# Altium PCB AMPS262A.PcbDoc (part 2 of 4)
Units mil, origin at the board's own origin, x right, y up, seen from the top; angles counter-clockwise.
Board outline 5314.96 x 4803.15 mil, 4 copper layers (Top Layer, GND, Copper Layer 3, Bottom Layer), stack 79.28 mil thick; 324 components, 156 nets, 943 pads, 1411 vias.
Unrouted connection lines stored in the file: 130.
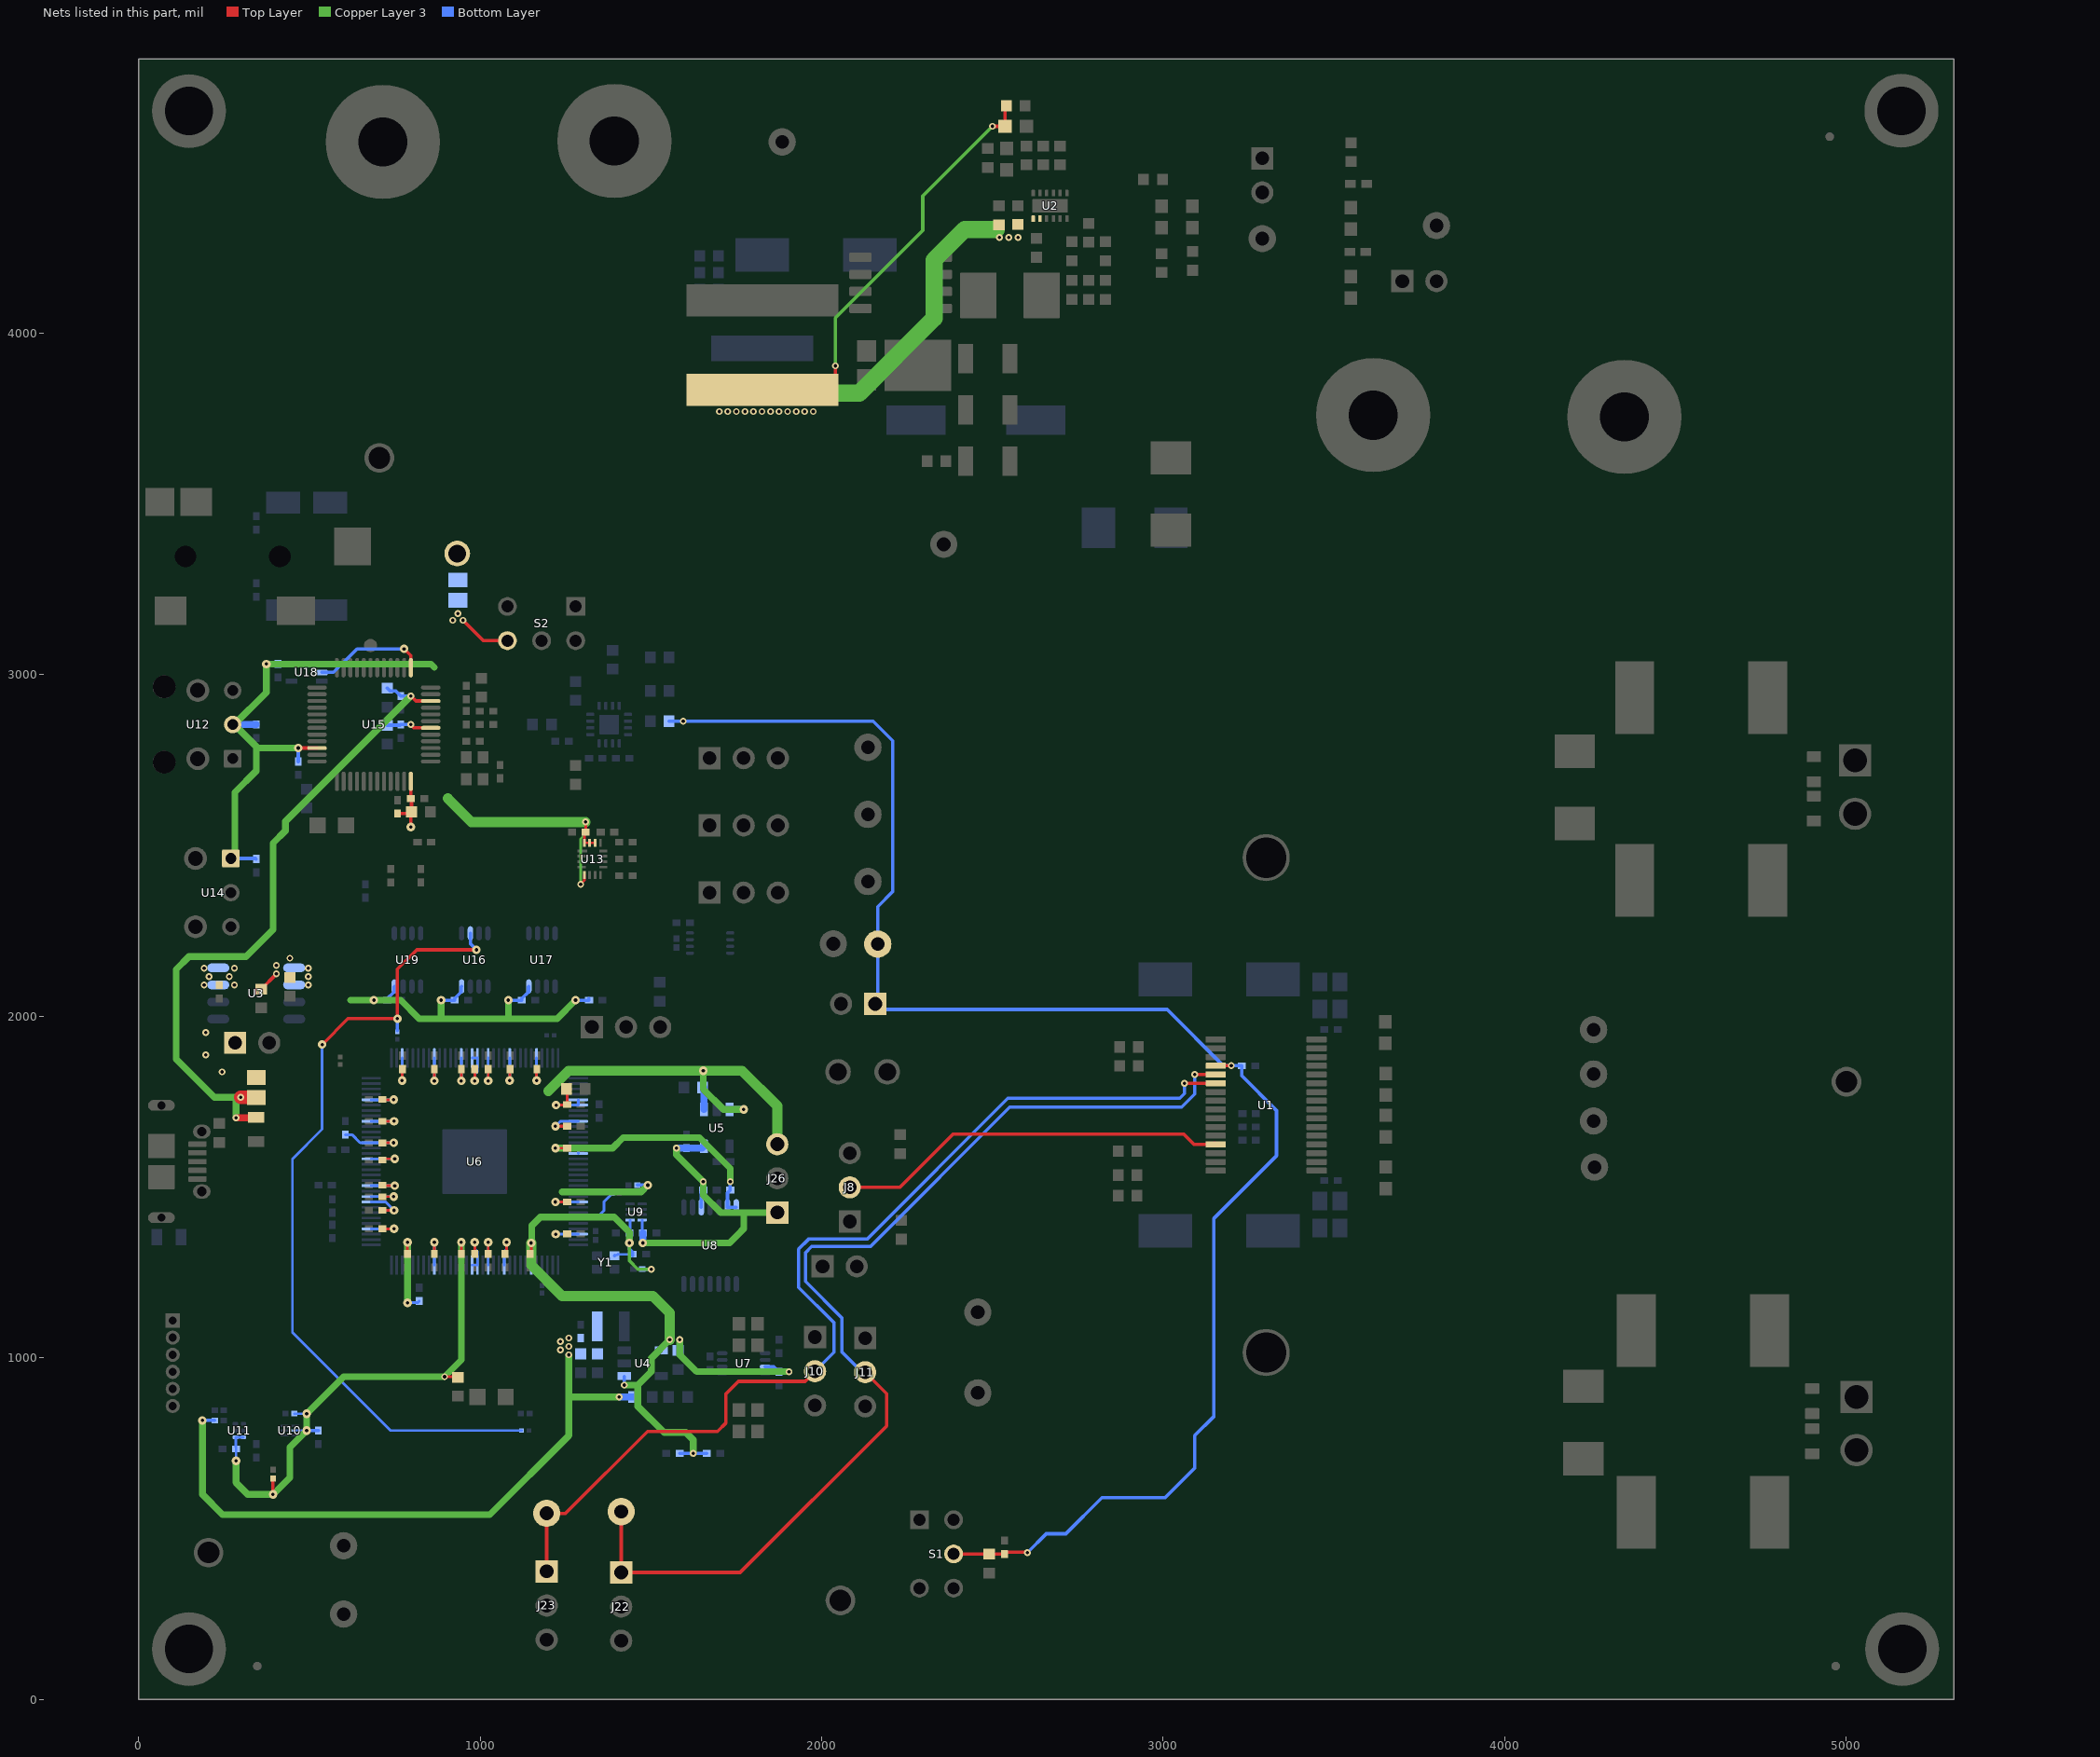
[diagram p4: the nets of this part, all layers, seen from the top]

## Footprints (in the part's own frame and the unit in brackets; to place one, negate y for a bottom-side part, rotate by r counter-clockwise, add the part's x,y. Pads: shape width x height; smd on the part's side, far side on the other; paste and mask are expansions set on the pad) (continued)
TQFP-128 [mm] "TQFP, 128-Leads, Body 14x14mm, Pitch 0.4mm"
  rrect50% 1.45x0.2 smd: 1(-7.7,6.2) 2(-7.7,5.8) 3(-7.7,5.4) 4(-7.7,5) 5(-7.7,4.6) 6(-7.7,4.2) 7(-7.7,3.8) 8(-7.7,3.4) 9(-7.7,3) 10(-7.7,2.6) 11(-7.7,2.2) 12(-7.7,1.8) 13(-7.7,1.4) 14(-7.7,1) 15(-7.7,0.6) 16(-7.7,0.2) 17(-7.7,-0.2) 18(-7.7,-0.6) 19(-7.7,-1) 20(-7.7,-1.4) 21(-7.7,-1.8) 22(-7.7,-2.2) 23(-7.7,-2.6) 24(-7.7,-3) 25(-7.7,-3.4) 26(-7.7,-3.8) 27(-7.7,-4.2) 28(-7.7,-4.6) 29(-7.7,-5) 30(-7.7,-5.4) 31(-7.7,-5.8) 32(-7.7,-6.2) 65(7.7,-6.2) 66(7.7,-5.8) 67(7.7,-5.4) 68(7.7,-5) 69(7.7,-4.6) 70(7.7,-4.2) 71(7.7,-3.8) 72(7.7,-3.4) 73(7.7,-3) 74(7.7,-2.6) 75(7.7,-2.2) 76(7.7,-1.8) 77(7.7,-1.4) 78(7.7,-1) 79(7.7,-0.6) 80(7.7,-0.2) 81(7.7,0.2) 82(7.7,0.6) 83(7.7,1) 84(7.7,1.4) 85(7.7,1.8) 86(7.7,2.2) 87(7.7,2.6) 88(7.7,3) 89(7.7,3.4) 90(7.7,3.8) 91(7.7,4.2) 92(7.7,4.6) 93(7.7,5) 94(7.7,5.4) 95(7.7,5.8) 96(7.7,6.2)
  rrect50% 0.2x1.45 smd: 33(-6.2,-7.7) 34(-5.8,-7.7) 35(-5.4,-7.7) 36(-5,-7.7) 37(-4.6,-7.7) 38(-4.2,-7.7) 39(-3.8,-7.7) 40(-3.4,-7.7) 41(-3,-7.7) 42(-2.6,-7.7) 43(-2.2,-7.7) 44(-1.8,-7.7) 45(-1.4,-7.7) 46(-1,-7.7) 47(-0.6,-7.7) 48(-0.2,-7.7) 49(0.2,-7.7) 50(0.6,-7.7) 51(1,-7.7) 52(1.4,-7.7) 53(1.8,-7.7) 54(2.2,-7.7) 55(2.6,-7.7) 56(3,-7.7) 57(3.4,-7.7) 58(3.8,-7.7) 59(4.2,-7.7) 60(4.6,-7.7) 61(5,-7.7) 62(5.4,-7.7) 63(5.8,-7.7) 64(6.2,-7.7) 97(6.2,7.7) 98(5.8,7.7) 99(5.4,7.7) 100(5,7.7) 101(4.6,7.7) 102(4.2,7.7) 103(3.8,7.7) 104(3.4,7.7) 105(3,7.7) 106(2.6,7.7) 107(2.2,7.7) 108(1.8,7.7) 109(1.4,7.7) 110(1,7.7) 111(0.6,7.7) 112(0.2,7.7) 113(-0.2,7.7) 114(-0.6,7.7) 115(-1,7.7) 116(-1.4,7.7) 117(-1.8,7.7) 118(-2.2,7.7) 119(-2.6,7.7) 120(-3,7.7) 121(-3.4,7.7) 122(-3.8,7.7) 123(-4.2,7.7) 124(-4.6,7.7) 125(-5,7.7) 126(-5.4,7.7) 127(-5.8,7.7) 128(-6.2,7.7)
  rrect2% 4.8x4.8 smd paste-4.8: 129(0,0)
  silkscreen extent -7.1,-7.1 7.1,7.1, body extent -7,-7 7,7, height 1.2
WE-PD_1210 [mm] "Wurth Elektronik recommended land pattern"
  rect 2.9x5.4 smd: 1(-4.95,0) 2(4.95,0)
  silkscreen extent -6,-6 6,6, body extent -6,-6 6,6, height 10.01
WEEE_Minimum [mil] "WEEElie bin"
  silkscreen extent -95,-172 99,104
XAL1010 [mm] "COILCRAFT"
  rect 2.38x11.31 smd: 1(-3.325,0) 2(3.325,0)
  silkscreen extent -5.3,-6 5.3,6, body extent -5.25,-5.9 5.25,5.9, height 10
XTAL_ABM10 [mm] "ABRACON"
  rect 0.8x0.9 smd: 1(-0.625,0.825) 2(-0.625,-0.825) 3(0.625,-0.825) 4(0.625,0.825)
  silkscreen extent -1.28,-0.13 1.05,1.52, body extent -1.05,-1.3 1.05,1.3, height 0.7

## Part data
C1 C10 C13 C21: library part CMP-0086459-1, "CAP CER 0.68UF 50V X7R 0805", Manufacturer="TDK Corporation", TempCo=15%, Tolerance_%=20%
C2 C7: library part CMP-0007842-2, "CAP, CERM, 10 uF, 35 V, +/- 10%, X5R, 0805", Alternate Manufacturer="CAL-CHIP ELECTRONICS, INC.", Alternate PartNumber=GMC21X5R106K35NT, Cap_Case=0805, Manufacturer=TDK, Supplier Part Number 1=445-14417-1-ND, TempCo=X5R, Tolerance_%=10%, Value1="0.002818 ohm", Value2=35V, ValueDisplayed=10uF
C3 C6: library part CMP-0007842-2, "CAP, CERM, 10 uF, 35 V, +/- 10%, X5R, 0805", Alternate Manufacturer="CAL-CHIP ELECTRONICS, INC.", Alternate PartNumber=GMC21X5R106K35NT, Cap_Case=0805, Manufacturer=TDK, PartNumber=C2012X5R1V106K085AC, Supplier Part Number 1=445-14417-1-ND, TempCo=X5R, Tolerance_%=10%, Value1="0.002818 ohm", Value2=35V, ValueDisplayed=10uF
C4 C5: library part CMP-0006325-2, "CAP, CERM, 0.1 uF, 50 V, +/- 10%, X7R, AEC-Q200 Grade 1, 0402", Cap_Case=0402, Manufacturer=TDK, Supplier Part Number 1=445-6899-1-ND, TempCo=X7R, Tolerance_%=10%, Value1="0.039064 ohm", Value2=50V, ValueDisplayed=0.1uF
C8 C9: library part CMP-0011092-1, "CAP, AL, 390 uF, 35 V, +/- 20%, 0.08 ohm, SMD", Cap_Case=10x10, Manufacturer=Nichicon, PartNumber=UCL1V391MNL1GS, Supplier Part Number 1=493-3960-1-ND, Tolerance_%=20%, Value1="0.08 ohm", Value2=35V, ValueDisplayed=390uF
C11: library part CMP-0006949-5, "CAP, CERM, 4.7 uF, 10 V, +/- 10%, X5R, 0603", Cap_Case=0603, Manufacturer=Kemet, PartNumber=C0603C475K8PACTU, Supplier Part Number 1=399-5503-1-ND, TempCo=X5R, Tolerance_%=10%, Value1="0.006 ohm", Value2=10V, ValueDisplayed=4.7uF
C12 C22: library part CMP-0006860-5, "CAP, CERM, 0.1 uF, 16 V, +/- 10%, X7R, 0603", Cap_Case=0603, Manufacturer=Kemet, PartNumber=C0603C104K4RACTU, Supplier Part Number 1=399-1096-1-ND, TempCo=X7R, Tolerance_%=10%, Value1=Unknown, Value2=16V, ValueDisplayed=0.1uF
C14 C16 C18 C20: library part CMP-0007050-4, "CAP, CERM, 0.47 uF, 50 V, +/- 10%, X7R, 0603", Cap_Case=0603, Manufacturer=TDK, Supplier Part Number 1=445-5952-1-ND, TempCo=X7R, Tolerance_%=10%, Value1="0.010974 ohm", Value2=50V, ValueDisplayed=0.47uF
C15 C17 C19: library part CMP-0082012-1, "CAP, CERM, 1 µF, 16 V,+/- 20%, X7R, 0603", Cap_Case=0603, Manufacturer=Samsung, Supplier Part Number 1=1276-6524-1-ND, TempCo=X7R, Tolerance_%=20%, Value2=16V, ValueDisplayed=1µF
C23: library part CMP-0012596-3, "CAP, Polymer Hybrid, 100 uF, 50 V, +/- 20%, 28 ohm, 10x10 SMD", Alternate Manufacturer="Cornell Dubilier Electronics (CDE)", Alternate PartNumber=HZA107M050G24VT-F, Manufacturer=Panasonic, PartNumber=EEHZC1H101P, Supplier Part Number 1=P15462CT-ND, Tolerance_%=20%, Value1="28 ohm", Value2=50V, ValueDisplayed=100uF
C24 C25 C26: library part CMP-0860569-1, "CAP, CERM, 10 µF, 25 V,+/- 10%, X5R, 0603", Alternate Manufacturer="CAL-CHIP ELECTRONICS, INC.", Alternate PartNumber=GMC10X5R106K25NT, Cap_Case=0603, Manufacturer=MuRata, TempCo=X5R, Tolerance_%=10%, Value2=25V, ValueDisplayed=10µF
C27: library part CMP-0080610-1, "CAP, CERM, 0.1 µF, 25 V,+/- 10%, X7R, AEC-Q200 Grade 1, 0402", Cap_Case=0402, Manufacturer=TDK, Supplier Part Number 1=445-6902-1-ND, TempCo=X7R, Tolerance_%=10%, Value2=25V, ValueDisplayed=0.1µF
C28: library part CMP-0007078-4, "CAP, CERM, 0.1 uF, 50 V, +/- 10%, X7R, AEC-Q200 Grade 1, 0603", Cap_Case=0603, Manufacturer=TDK, Supplier Part Number 1=445-5666-1-ND, TempCo=X7R, Tolerance_%=10%, Value1="0.0296 ohm", Value2=50V, ValueDisplayed=0.1uF
C29 C30 C31: library part CMP-0009162-2, "CAP, CERM, 4.7 uF, 50 V, +/- 10%, X7R, AEC-Q200 Grade 1, 1210", Cap_Case=1210_280, Manufacturer=TDK, Supplier Part Number 1=445-6999-1-ND, TempCo=X7R, Tolerance_%=10%, Value1="0.003166 ohm", Value2=50V, ValueDisplayed=4.7uF
C32: library part CMP-0012269-3, "CAP, Aluminum Polymer, 100 uF, 50 V, +/- 20%, 0.025 ohm, AEC-Q200 Grade 2, D10xL10mm SMD", Alternate Manufacturer="Cornell Dubilier Electronics (CDE)", Alternate PartNumber=HZA107M050G24VT-F, Cap_Case=10x10mm, Manufacturer=Chemi-Con, PartNumber=HHXB500ARA101MJA0G, Supplier Part Number 1=565-4187-1-ND, Tolerance_%=20%, Value1="0.025 ohm", Value2=50V, ValueDisplayed=100uF
C33: library part CMP-0007137-5, "CAP, CERM, 1 uF, 16 V, +/- 20%, X7R, AEC-Q200 Grade 1, 0603", Cap_Case=0603, Manufacturer=MuRata, TempCo=X7R, Tolerance_%=20%, Value1=Unknown, Value2=16V, ValueDisplayed=1uF
C34: library part CMP-0007143-4, "CAP, CERM, 0.01 uF, 50 V, +/- 10%, X7R, AEC-Q200 Grade 1, 0603", Cap_Case=0603, Manufacturer=MuRata, Supplier Part Number 1=490-4778-1-ND, TempCo=X7R, Tolerance_%=10%, Value1=Unknown, Value2=50V, ValueDisplayed=0.01uF
C35: library part CMP-0080091-1, "CAP, CERM, 100 pF, 50 V,+/- 1%, C0G/NP0, 0603", Cap_Case=0603, Manufacturer=Kemet, PartNumber=C0603C101F5GACTU, Supplier Part Number 1=399-7819-1-ND, TempCo=C0G/NP0, Tolerance_%=1%, Value2=50V, ValueDisplayed=100pF
C36: library part CMP-0080091-1, "CAP, CERM, 100 pF, 50 V,+/- 1%, C0G/NP0, 0603", Cap_Case=0603, Manufacturer=Kemet, Supplier Part Number 1=399-7819-1-ND, TempCo=C0G/NP0, Tolerance_%=1%, Value2=50V, ValueDisplayed=100pF
C37: library part CMP-0007094-5, "CAP, CERM, 0.22 uF, 50 V, +/- 10%, X7R, AEC-Q200 Grade 1, 0603", Cap_Case=0603, Manufacturer=TDK, Supplier Part Number 1=445-6926-1-ND, TempCo=X7R, Tolerance_%=10%, Value1="0.021699 ohm", Value2=50V, ValueDisplayed=0.22uF
C38: library part CMP-0007072-4, "CAP, CERM, 220 pF, 20 V, +/- 5%, C0G/NP0, AEC-Q200 Grade 1, 0603", Cap_Case=0603, Manufacturer=TDK, Supplier Part Number 1=445-5644-1-ND, TempCo=C0G/NP0, Tolerance_%=5%, Value1=Unknown, Value2=20V, ValueDisplayed=220pF
C39: library part CMP-0006900-4, "CAP, CERM, 0.022 uF, 16 V, +/- 10%, X7R, 0603", Cap_Case=0603, Manufacturer=Kemet, Supplier Part Number 1=399-1093-1-ND, TempCo=X7R, Tolerance_%=10%, Value1=Unknown, Value2=16V, ValueDisplayed=0.022uF
C40 C41: library part CMP-0079606-1, "CAP, CERM, 220 pF, 50 V,+/- 5%, C0G/NP0, AEC-Q200 Grade 1, 0402", Cap_Case=0402, Manufacturer=TDK, Supplier Part Number 1=445-5600-1-ND, TempCo=C0G/NP0, Tolerance_%=5%, Value2=50V, ValueDisplayed=220pF
C42 C44 C45 C46 C47 C48 C49 C50 C51 C52 C53 C54 C55 C56 C57 C61 C65 C66 C67 C68 C69 C70 C71 C72 C73 C74 C75 C76 C77 C78 C79 C80 C81 C82 C83 C85 C86 C88 C89 C90 C91 C92 C93 C94 C95 C97 C99 C100 C104 C111 C114 C115 C116 C117 C118 C119 C120: library part CMP-0006228-2, "CAP, CERM, 0.1 uF, 16 V, +/- 10%, X7R, 0402", Cap_Case=0402, Manufacturer="Wurth Elektronik", Supplier Part Number 1=732-7532-1-ND, TempCo=X7R, Tolerance_%=10%, Value1=Unknown, Value2=16V, ValueDisplayed=0.1uF
C43: library part CMP-0007003-5, "CAP, CERM, 10 uF, 10 V, +/- 20%, X5R, 0603", Cap_Case=0603, Manufacturer=TDK, PartNumber=C1608X5R1A106M080AC, Supplier Part Number 1=445-6853-1-ND, TempCo=X5R, Tolerance_%=20%, Value1="0.0078 ohm", Value2=10V, ValueDisplayed=10uF
C58 C59 C60: library part CMP-0007005-5, "CAP, CERM, 22 uF, 10 V, +/- 20%, X5R, 0603", Cap_Case=0603, Manufacturer=TDK, Supplier Part Number 1=445-9077-1-ND, TempCo=X5R, Tolerance_%=20%, Value1="0.00371 ohm", Value2=10V, ValueDisplayed=22uF
C62: library part CMP-0007003-5, "CAP, CERM, 10 uF, 10 V, +/- 20%, X5R, 0603", Cap_Case=0603, Manufacturer=TDK, Supplier Part Number 1=445-6853-1-ND, TempCo=X5R, Tolerance_%=20%, Value1="0.0078 ohm", Value2=10V, ValueDisplayed=10uF
C63: library part CMP-0006372-2, "CAP, CERM, 1 uF, 6.3 V, +/- 20%, X5R, 0402", Cap_Case=0402, Manufacturer=MuRata, Supplier Part Number 1=490-10006-1-ND, TempCo=X5R, Tolerance_%=20%, Value1=Unknown, Value2=6.3V, ValueDisplayed=1uF
C64: library part CMP-0006227-2, "CAP, CERM, 0.01 uF, 16 V, +/- 10%, X7R, 0402", Cap_Case=0402, Manufacturer="Wurth Elektronik", Supplier Part Number 1=710-885012205031, TempCo=X7R, Tolerance_%=10%, Value1=Unknown, Value2=16V, ValueDisplayed=0.01uF
C84: library part CMP-0006470-2, "CAP, CERM, 470 pF, 50 V, +/- 5%, C0G/NP0, 0402", Cap_Case=0402, Manufacturer=MuRata, Supplier Part Number 1=490-1297-1-ND, TempCo=C0G/NP0, Tolerance_%=5%, Value1=Unknown, Value2=50V, ValueDisplayed=470pF
C87: library part CMP-0007370-4, "CAP, CERM, 2.2 uF, 10 V, +/- 10%, X7R, 0603", Cap_Case=0603, Manufacturer=MuRata, PartNumber=GRM188R71A225KE15D, Supplier Part Number 1=490-4520-1-ND, TempCo=X7R, Tolerance_%=10%, Value1="0.009 ohm", Value2=10V, ValueDisplayed=2.2uF
C96 C98 C101 C110: library part CMP-0007122-5, "CAP, CERM, 10 uF, 16 V, +/- 20%, X5R, 0603", Alternate Manufacturer="CAL-CHIP ELECTRONICS, INC.", Alternate PartNumber=GMC10X5R106M16NT, Cap_Case=0603, Manufacturer="Taiyo Yuden", Supplier Part Number 1=587-3238-1-ND, TempCo=X5R, Tolerance_%=20%, Value1=Unknown, Value2=16V, ValueDisplayed=10uF
C102 C103 C107: library part CMP-0006215-2, "CAP, CERM, 10 pF, 50 V, +/- 5%, C0G/NP0, 0402", Cap_Case=0402, Manufacturer="Wurth Elektronik", Supplier Part Number 1=732-7469-1-ND, TempCo=C0G/NP0, Tolerance_%=5%, Value1=Unknown, Value2=50V, ValueDisplayed=10pF
C105 C106: library part CMP-0006365-2, "CAP, CERM, 27 pF, 50 V, +/- 5%, C0G/NP0, 0402", Cap_Case=0402, Manufacturer=MuRata, TempCo=C0G/NP0, Tolerance_%=5%, Value1=Unknown, Value2=50V, ValueDisplayed=27pF
C108 C109: library part CMP-0010644-1, "CAP, AL, 10 uF, 16 V, +/- 20%, 3 ohm, SMD", Cap_Case=B, Manufacturer=Panasonic, Supplier Part Number 1=PCE3995CT-ND, Tolerance_%=20%, Value1="3 ohm", Value2=16V, ValueDisplayed=10uF
C112: library part CMP-0860557-1, "CAP, CERM, 4700 pF, 25 V,+/- 10%, X7R, 0402", Cap_Case=0402, Manufacturer=Yageo, TempCo=X7R, Tolerance_%=10%, Value2=25V, ValueDisplayed=4700pF
C113: library part CMP-0006331-2, "CAP, CERM, 0.068 uF, 50 V, +/- 10%, X7R, AEC-Q200 Grade 1, 0402", Cap_Case=0402, Manufacturer=TDK, Supplier Part Number 1=445-6898-1-ND, TempCo=X7R, Tolerance_%=10%, Value1="0.05606 ohm", Value2=50V, ValueDisplayed=0.068uF
D1: library part CMP-0028984-3, "Diode, Schottky, 60 V, 10 A, AEC-Q101, CFP15", Alternate Manufacturer="Vishay General Semiconductor - Diodes Division", Alternate PartNumber=V10PM6-M3/H, Manufacturer=Nexperia, Value1=10A, Value2=0.56V
D2 D3: library part CMP-0002889-2, "LED, Blue, SMD", Color=Blue, Manufacturer=Lite-On, PartNumber=LTST-C170TBKT, Value1=W, Value2=3.3V
FID1 FID2 FID3 FID4 FID5 FID6: library part CMP-0077181-1, "Fiducial mark.  There is nothing to buy or mount.", Manufacturer=N/A
H1: library part CMP-0004031-2, "Heat Sink, Vertical", Manufacturer="Advanced Thermal Solutions", Supplier Part Number 1=ATS2180-ND
H2 H3 H4 H5: library part CMP-0003717-1, "MACHINE SCREW PAN PHILLIPS M3", Manufacturer="APM HEXSEAL", PartNumber="RM3X8MM 2701", Supplier Part Number 1=335-1149-ND
H6 H7 H8 H9: library part CMP-0003665-1, "Standoff, Hex, 12mm, M3, Aluminum", Manufacturer=Keystone, PartNumber=24434, Supplier Part Number 1=36-24434-ND
J1 J7 J14 J18: library part CMP-0075020-1, "JUMPER TIN SMD", Manufacturer=Harwin, PartNumber=S1911-46R, Supplier Part Number 1=952-1740-1-ND
J2 J6: library part CMP-0074989-1, "Header (friction lock), 3.96mm, 2x1, Tin, R/A, TH", Alternate Manufacturer="JST Sales America Inc.", Alternate PartNumber=S2P-VH(LF)(SN), Manufacturer="JST Manufacturing", PartNumber=B2PS-VH(LF)(SN), Supplier Part Number 1=455-1648-ND
J3 J9 J15 J16 J19: library part CMP-0054566-1, "Header, 100mil, 2x1, Gold, TH", Color=Black, Current_A=3A, Manufacturer="Sullins Connector Solutions", PartNumber=PBC02SAAN, Supplier Part Number 1=S1011E-02-ND, Voltage_V=1.8kV
J4 J5 J21: library part CMP-0055161-1, Manufacturer=Keystone, PartNumber=1040, Supplier Part Number 1=36-1040-ND
J8 J10 J11 J22 J23 J26 J27 J28 J29 J31: library part CMP-0002334-1, "Header, 100mil, 3x1, Gold, TH", Manufacturer="Sullins Connector Solutions", PartNumber=PBC03SAAN, Supplier Part Number 1=S1011E-03-ND
J12 J17: library part CMP-0055127-1, "Binding Post, RED, TH", Manufacturer=Keystone, PartNumber=7006, Supplier Part Number 1=36-7006-ND
J13 J20: library part CMP-0055128-1, "Binding Post, BLACK, TH", Manufacturer=Keystone, PartNumber=7007, Supplier Part Number 1=36-7007-ND
J24: library part CMP-0054640-1, "Receptacle, 50mil, 6x1, Gold, R/A, TH", Color=Black, Manufacturer="Sullins Connector Solutions", PartNumber=LPPB061NGCN-RC, Supplier Part Number 1=S9010E-06-ND
J25: library part CMP-0055301-1, "Connector, Receptacle, Micro-USB Type AB, R/A, Bottom Mount SMT", Manufacturer=Molex, PartNumber=475890001, Supplier Part Number 1=WM17143CT-ND
J30: library part CMP-0074987-1, "Audio Jack, 3.5mm, Stereo, R/A, SMT", Manufacturer=Switchcraft, PartNumber=35RASMT4BHNTRX, Supplier Part Number 1=SC1488-1-ND
L1 L2 L3 L4: library part CMP-0064206-1, "Inductor, Shielded Drum Core, Ferrite, 10 uH, 7.1 A, 0.01294 ohm, SMD", Manufacturer="Wurth Elektronik", Supplier Part Number 1=732-1241-1-ND, Value1="0.01294 ohm", Value2=7.1A, ValueDisplayed=10uH
L5: library part CMP-0060953-1, "Inductor, Shielded, Composite, 6.8 uH, 18.5 A, 0.01 ohm, SMD", Manufacturer=Coilcraft, Supplier Part Number 1=994-XAL1010-682MEB, Value1="0.01 ohm", Value2=18.5A, ValueDisplayed=6.8uH
L6: library part CMP-0058752-1, "Inductor, Multilayer, Ferrite, 2.2 uH, 1.3 A, 0.08 ohm, SMD", Manufacturer=MuRata, Supplier Part Number 1=490-5114-1-ND, Value1="0.08 ohm", Value2=1.3A, ValueDisplayed=2.2uH
L7 L8: library part CMP-0003429-3, "Ferrite Bead, 600 ohm @ 100 MHz, 2 A, 0805", Manufacturer=TDK, Supplier Part Number 1=445-2206-1-ND, Value1="0.1 ohm", Value2=2A, ValueDisplayed="600 ohm"
Logo1: library part CMP-0074844-2, Manufacturer="Texas Instruments"
Logo2: library part CMP-0074838-1, "Texas Instrument Corporate Signature"
Logo3: library part CMP-0074847-1, "FCC_disclaimer"
Logo4: library part CMP-0074769-4, Manufacturer="Texas Instruments"
Q1: library part CMP-0080659-3, "MOSFET, N-CH, 40 V, 50 A, AEC-Q101, SON-8", Alternate Manufacturer="Texas Instruments", Alternate PartNumber=CSD18510Q5B, Manufacturer="Infineon Technologies", Supplier Part Number 1=IPC50N04S5L5R5ATMA1CT-ND, Value1="0.0079 ohm", Value2="17 nC"
R1 R6 R15 R17 R22 R25 R26 R30 R73 R74 R75 R76 R77 R78 R80: library part CMP-0025885-5, "RES, 0, 5%, 0.1 W, 0603", Manufacturer=Yageo, Power_W=100mW, Supplier Part Number 1=311-0.0GRCT-ND, TempCo="200 ppm/C", Tolerance_%=5%, Value2=0.1W, Value_Code=0000, ValueDisplayed=0
R2: library part CMP-0065359-1, "RES, 15.0 k, .1%, .063 W, AEC-Q200 Grade 0, 0402", Manufacturer=Panasonic, PartNumber=ERA-2AEB153X, Power_W=63mW, Supplier Part Number 1=P15KDCCT-ND, TempCo="25 ppm/C", Tolerance_%=0.1%, Value1=.1%, Value2=.063W, Value_Code=15k0, ValueDisplayed=10.0k
R3 R36: library part CMP-0026852-3, "RES, 1.0 k, 5%, 0.063 W, AEC-Q200 Grade 0, 0402", Alternate Manufacturer="Vishay Dale", Alternate PartNumber=CRCW04021K00JNTD, Manufacturer=Vishay-Dale, PartNumber=CRCW04021K00JNED, Power_W=63mW, Supplier Part Number 1=541-1.0KJCT-ND, TempCo="200 ppm/C", Tolerance_%=5%, Value2=0.063W, Value_Code=1k00, ValueDisplayed=1.0k
R4 R5 R7 R66 R79: library part CMP-0025958-3, "RES, 10.0 k, 1%, 0.063 W, AEC-Q200 Grade 0, 0402", Manufacturer=Vishay-Dale, PartNumber=CRCW040210K0FKED, Power_W=63mW, Supplier Part Number 1=541-10.0KLCT-ND, TempCo="100 ppm/C", Tolerance_%=1%, Value2=0.063W, Value_Code=10k0, ValueDisplayed=10.0k
R8 R9: library part CMP-0025906-5, "RES, 2.2 k, 5%, 0.1 W, 0603", Manufacturer=Yageo, Power_W=100mW, Supplier Part Number 1=311-2.2KGRCT-ND, TempCo="100 ppm/C", Tolerance_%=5%, Value2=0.1W, Value_Code=2k20, ValueDisplayed=2.2k
R10 R11: library part CMP-0025899-5, "RES, 1.0 k, 5%, 0.1 W, 0603", Manufacturer=Yageo, Power_W=100mW, Supplier Part Number 1=311-1.0KGRCT-ND, TempCo="100 ppm/C", Tolerance_%=5%, Value2=0.1W, Value_Code=1k00, ValueDisplayed=1.0k
R12: library part CMP-0015368-2, "RES, 0, 5%, 2 W, 2512 WIDE", Manufacturer="Vishay Draloric", Power_W=2W, Supplier Part Number 1=RCL0.0ECT-ND, TempCo=ppm/C, Tolerance_%=5%, Value_Code=0000, ValueDisplayed=0
R13 R19: library part CMP-0022914-5, "RES, 21.0 k, 1%, 0.1 W, 0603", Manufacturer=Yageo, Power_W=100mW, Supplier Part Number 1=311-21.0KHRCT-ND, TempCo="100 ppm/C", Tolerance_%=1%, Value2=0.1W, Value_Code=21k0, ValueDisplayed=21.0k
R14 R64: library part CMP-0023343-3, "RES, 0, 1%, 0.1 W, AEC-Q200 Grade 0, 0603", Manufacturer="Stackpole Electronics Inc", Power_W=100mW, Supplier Part Number 1=RMCF0603ZT0R00CT-ND, TempCo=ppm/C, Tolerance_%=1%, Value2=0.1W, Value_Code=0
R16: library part CMP-0022944-5, "RES, 24.9 k, 1%, 0.1 W, 0603", Manufacturer=Yageo, Power_W=100mW, Supplier Part Number 1=311-24.9KHRCT-ND, TempCo="100 ppm/C", Tolerance_%=1%, Value2=0.1W, Value_Code=24k9, ValueDisplayed=24.9k
R18: library part CMP-0022736-4, "RES, 100, 1%, 0.1 W, 0603", Manufacturer=Yageo, Power_W=100mW, Supplier Part Number 1=311-100HRCT-ND, TempCo="100 ppm/C", Tolerance_%=1%, Value2=0.1W, Value_Code=100R, ValueDisplayed=100
R20: library part CMP-0022447-4, "RES, 49.9 k, 1%, 0.1 W, AEC-Q200 Grade 0, 0603", Manufacturer=Vishay-Dale, Power_W=100mW, Supplier Part Number 1=541-49.9KHCT-ND, TempCo="100 ppm/C", Tolerance_%=1%, Value2=0.1W, Value_Code=49k9, ValueDisplayed=49.9k
R21: library part CMP-0015077-2, "RES, 0.004, 1%, 3 W, AEC-Q200 Grade 0, 6.4x3.2mm", Alternate Manufacturer="TE Connectivity Passive Product", Alternate PartNumber=TLRP3A30WR004FTE, Manufacturer=Panasonic, Power_W=3W, Supplier Part Number 1=P17092CT-ND, TempCo="75 ppm/C", Tolerance_%=1%, Value_Code=4L000, ValueDisplayed=0.004
R23: library part CMP-0023239-5, "RES, 68.0 k, 1%, 0.1 W, 0603", Manufacturer=Yageo, Power_W=100mW, Supplier Part Number 1=311-68.0KHRCT-ND, TempCo="100 ppm/C", Tolerance_%=1%, Value2=0.1W, Value_Code=68k0, ValueDisplayed=68.0k
R24: library part CMP-0022017-4, "RES, 11.3 k, 1%, 0.1 W, AEC-Q200 Grade 0, 0603", Manufacturer=Vishay-Dale, Power_W=100mW, Supplier Part Number 1=541-11.3KHCT-ND, TempCo="100 ppm/C", Tolerance_%=1%, Value2=0.1W, Value_Code=11k3, ValueDisplayed=11.3k
R27 R28: library part CMP-0022684-3, "RES, 10.0 k, 1%, 0.1 W, 0603", Manufacturer=Panasonic, Power_W=100mW, Supplier Part Number 1=P10.0KHCT-ND, TempCo="100 ppm/C", Tolerance_%=1%, Value2=0.1W, Value_Code=10k0, ValueDisplayed=10.0k
R29: library part CMP-0023148-5, "RES, 4.30 k, 1%, 0.1 W, 0603", Manufacturer=Yageo, Power_W=100mW, Supplier Part Number 1=311-4.30KHRCT-ND, TempCo="100 ppm/C", Tolerance_%=1%, Value2=0.1W, Value_Code=4k30, ValueDisplayed=4.30k
R31 R33: library part CMP-0020803-2, "RES, 0, 5%, 0.125 W, 0805", Manufacturer="Yageo America", Power_W=125mW, Supplier Part Number 1=311-0.0ARCT-ND, TempCo="200 ppm/C", Tolerance_%=5%, Value2=0.125W, Value_Code=0000, ValueDisplayed=0
R32: library part CMP-0022941-4, "RES, 249 k, 1%, 0.1 W, 0603", Manufacturer=Yageo, Power_W=100mW, Supplier Part Number 1=311-249KHRCT-ND, TempCo="100 ppm/C", Tolerance_%=1%, Value2=0.1W, Value_Code=249k
R34: library part CMP-0023232-5, "RES, 66.5 k, 1%, 0.1 W, 0603", Manufacturer=Yageo, Power_W=100mW, Supplier Part Number 1=311-66.5KHRCT-ND, TempCo="100 ppm/C", Tolerance_%=1%, Value2=0.1W, Value_Code=66k5, ValueDisplayed=66.5k
R35: library part CMP-0022735-5, "RES, 100 k, 1%, 0.1 W, 0603", Manufacturer=Yageo, Power_W=100mW, Supplier Part Number 1=311-100KHRCT-ND, TempCo="100 ppm/C", Tolerance_%=1%, Value2=0.1W, Value_Code=100k
R37 R38: library part CMP-0026890-5, "RES, 2.2 k, 5%, 0.063 W, AEC-Q200 Grade 0, 0402", Manufacturer=Vishay-Dale, PartNumber=CRCW04022K20JNED, Power_W=63mW, Supplier Part Number 1=541-2.2KJCT-ND, TempCo="200 ppm/C", Tolerance_%=5%, Value2=0.063W, Value_Code=2k20, ValueDisplayed=2.2k
R39 R46: library part CMP-0026658-1, "RES, 10.0 k, 1%, 0.1 W, 0402", Alternate Manufacturer=Panasonic, Alternate PartNumber=ERJ-U02F1002X, PartNumber=ERJ-2RKF1002X, Power_W=100mW, Supplier Part Number 1=P10.0KLCT-ND, TempCo="100 ppm/C", Tolerance_%=1%, Value2=0.1W, Value_Code=10k0, ValueDisplayed=10.0k
R40: library part CMP-0025821-4, "RES, 4.7, 5%, 0.1 W, AEC-Q200 Grade 0, 0603", Manufacturer=Vishay-Dale, PartNumber=CRCW06034R70JNEA, Power_W=100mW, Supplier Part Number 1=541-4.7GCT-ND, TempCo="200 ppm/C", Tolerance_%=5%, Value2=0.1W, Value_Code=4R70, ValueDisplayed=4.7
R41: library part CMP-0026825-5, "RES, 10 k, 5%, 0.063 W, AEC-Q200 Grade 0, 0402", Alternate Manufacturer=Panasonic, Alternate PartNumber=ERJ-U02F1002X, Manufacturer=Vishay-Dale, PartNumber=CRCW040210K0JNED, Power_W=63mW, Supplier Part Number 1=541-10KJCT-ND, TempCo="200 ppm/C", Tolerance_%=5%, Value2=0.063W, Value_Code=10k0, ValueDisplayed=10k
R42 R43 R44 R47 R52 R53 R56: library part CMP-0027614-1, "RES, 33.2, 1%, 0.05 W, 0201", Manufacturer="Yageo America", PartNumber=RC0201FR-0733R2L, Power_W=50mW, Supplier Part Number 1=YAG2608CT-ND, TempCo="200 ppm/C", Tolerance_%=1%, Value2=0.05W, Value_Code=33R2, ValueDisplayed=33.2
R45: library part CMP-0023235-5, "RES, 680, 1%, 0.1 W, 0603", Manufacturer=Yageo, Power_W=100mW, Supplier Part Number 1=311-680HRCT-ND, TempCo="100 ppm/C", Tolerance_%=1%, Value2=0.1W, Value_Code=680R, ValueDisplayed=680
R48: library part CMP-0065361-1, "RES, 0, 5%, .05 W, AEC-Q200 Grade 0, 0201", Manufacturer=Panasonic, Power_W=50mW, Supplier Part Number 1=P15979CT-ND, TempCo=ppm/C, Tolerance_%=5%, Value2=.05W, Value_Code=0000, ValueDisplayed=0
R49: library part CMP-0082538-1, "RES, 43.2, 1%, 0.1 W, AEC-Q200 Grade 0, 0402", Manufacturer=Panasonic, Power_W=100mW, Supplier Part Number 1=P43.2LCT-ND, TempCo="100 ppm/C", Tolerance_%=1%, Value2=0.1W, Value_Code=43R2, ValueDisplayed=43.2
R50 R51 R55 R57 R72: library part CMP-0027262-3, "RES, 10.0 k, 1%, 0.05 W, 0201", Manufacturer=Vishay-Dale, PartNumber=CRCW020110K0FKED, Power_W=50mW, Supplier Part Number 1=541-10.0KAABCT-ND, TempCo="100 ppm/C", Tolerance_%=1%, Value2=0.05W, Value_Code=10k0, ValueDisplayed=10.0k
R54: library part CMP-0027523-1, "RES, 25.5 k, 1%, 0.05 W, 0201", Manufacturer="Yageo America", PartNumber=RC0201FR-0725K5L, Power_W=50mW, Supplier Part Number 1=YAG2538CT-ND, TempCo="200 ppm/C", Tolerance_%=1%, Value2=0.05W, Value_Code=25k5, ValueDisplayed=25.5k
R58: library part CMP-0027757-1, "RES, 51.0 k, 1%, 0.05 W, 0201", Manufacturer="Yageo America", PartNumber=RC0201FR-0751KL, Power_W=50mW, Supplier Part Number 1=311-51.0KMCT-ND, TempCo="200 ppm/C", Tolerance_%=1%, Value2=0.05W, Value_Code=51k0, ValueDisplayed=51.0k
R59: library part CMP-0026737-1, "RES, 47.0 k, 1%, 0.0625 W, 0402", Manufacturer="Yageo America", PartNumber=RC0402FR-0747KL, Power_W=62.5mW, Supplier Part Number 1=311-47.0KLRCT-ND, TempCo="100 ppm/C", Tolerance_%=1%, Value2=0.0625W, Value_Code=47k0, ValueDisplayed=47.0k
R60 R65 R67: library part CMP-0026404-2, "RES, 49.9, 1%, 0.063 W, AEC-Q200 Grade 0, 0402", Alternate Manufacturer=Vishay-Dale, Alternate PartNumber=CRCW040249R9FKEDC, PartNumber=CRCW040249R9FKED, Power_W=63mW, Supplier Part Number 1=541-49.9LCT-ND, TempCo="100 ppm/C", Tolerance_%=1%, Value2=0.063W, Value_Code=49R9, ValueDisplayed=49.9
R61 R62 R63: library part CMP-0026696-1, "RES, 33.0, 1%, 0.1 W, 0402", Alternate Manufacturer=Panasonic, Alternate PartNumber=ERJ-U02F33R0X, Power_W=100mW, Supplier Part Number 1=P33.0LCT-ND, TempCo="100 ppm/C", Tolerance_%=1%, Value2=0.1W, Value_Code=33R0, ValueDisplayed=33.0
R68: library part CMP-0025733-4, "RES, 1.5 k, 5%, 0.1 W, AEC-Q200 Grade 0, 0603", Alternate Manufacturer=Vishay-Dale, Alternate PartNumber=CRCW06031K50JNEAC, Power_W=100mW, Supplier Part Number 1=541-1.5KGCT-ND, TempCo="200 ppm/C", Tolerance_%=5%, Value2=0.1W, Value_Code=1k50, ValueDisplayed=1.5k
R69 R70: library part CMP-0026873-2, "RES, 200 k, 5%, 0.063 W, AEC-Q200 Grade 0, 0402", Manufacturer=Vishay-Dale, Power_W=63mW, Supplier Part Number 1=541-200KJCT-ND, TempCo="200 ppm/C", Tolerance_%=5%, Value2=0.063W, Value_Code=200k
R71: library part CMP-0026962-3, "RES, 680, 5%, 0.063 W, AEC-Q200 Grade 0, 0402", Manufacturer=Vishay-Dale, Power_W=63mW, Supplier Part Number 1=541-680JCT-ND, TempCo="200 ppm/C", Tolerance_%=5%, Value2=0.063W, Value_Code=680R, ValueDisplayed=680
S1 S2: library part CMP-0002209-2, "Switch, SPDT, On-On, 2 Pos, TH", CurrentRating_mA=400A, Manufacturer=E-Switch, PartNumber=200USP1T1A1M2RE, Supplier Part Number 1=EG4915-ND
SH-J1 SH-J2 SH-J3 SH-J4 SH-J5 SH-J6 SH-J7 SH-J8 SH-J9 SH-J10: library part CMP-0003623-3, "Shunt, 100mil, Gold plated, Black", Alternate Manufacturer=3M, Alternate PartNumber=969102-0000-DA, Manufacturer=Samtec, Supplier Part Number 1=SAM8858-ND
TP1 TP2 TP3 TP4 TP5 TP6 TP7 TP8 TP13 TP14 TP16 TP17 TP18 TP19 TP20 TP21 TP22 TP23 TP24: library part CMP-0055140-2, "Test Point, Miniature, Orange, TH", Color=Orange, Manufacturer="Keystone Electronics", PartNumber=5003, Supplier Part Number 1=36-5003-ND
TP9 TP10 TP11 TP12: library part CMP-0055143-2, "Test Point, Compact, Black, TH", Color=Black, Manufacturer="Keystone Electronics", PartNumber=5006, Supplier Part Number 1=36-5006-ND
TP15: library part CMP-0003825-1, "1mm Test Point, SMT", Manufacturer=Any, PartNumber=TP_SM_1MM
U1: library part CMP-0124450-1, Manufacturer="Texas Instruments", Operating Temperature Range=to
U2: library part CMP-0085413-1, "2.2-MHz Wide Input Nonsynchronous Boost, Sepic, Flyback Controller, DSS0012B (WSON-12)", Alternate Manufacturer="Texas Instruments", Alternate PartNumber=LM5155DSST
U3: library part CMP-0036485-1, "Single Output Fast Transient Response LDO, 1 A, Fixed 3.3 V Output, 2.7 to 10 V Input, with Low IQ, 8-pin SOIC (D), -40 to 125 degC, Green (RoHS & no Sb/Br)", Manufacturer="Texas Instruments", PartNumber=TPS76833QDR, Power Good=TRUE
U4: library part CMP-0013046-2, "1-A High Efficiency Step-Down Converter in SOT23-5 Package, DBV005A, DBV0005A (SOT-5)", Alternate Manufacturer="Texas Instruments", Alternate PartNumber=TLV62568DBVT
U5: library part CMP-0036854-2, "Single Output LDO, 400mA, Adj.(1.2 to 5.5V), Cap free, Low Noise, Reverse Current Protection, DBV0005A (SOT-23-5)", Manufacturer="Texas Instruments", PartNumber=TPS73618DBVR, Rating=Catalog
U6: library part CMP-0092035-2, "XCore XEF Microcontroller IC 32-Bit 16-Core 2000MIPs 2MB (2M x 8) FLASH 128-TQFP (14x14)", Digikey Part Number=880-XEF216-512-TQ128-C20A-ND, Frequency_Fixed=24MHz, Manufacturer=XMOS, Max Supply Voltage=3.465V, Min Supply Voltage=950mV, Nominal Supply Current=570mA, Operating Temperature Range="0°C to +70°C"
U7: library part CMP-0043323-2, "2-Bit Bidirectional 1-MHz I2C Bus and SMBus Voltage-Level Shifter, DCU0008A (VSSOP-8)", 5V Tolerant I/O=Yes, Manufacturer="Texas Instruments", Max Frequency(kHz)=1000, On-Chip Power-on-Reset=No, Operating Temperature Range="-40 to 85 C", Rating=Catalog
U8: library part CMP-0065668-3, "Programmable 1-PLL VCXO Clock Synthesizer with 2.5-V or 3.3-V LVCMOS Outputs, PW0014A (TSSOP-14)", Alternate Manufacturer="Texas Instruments", Alternate PartNumber=CDCE913PW, Operating Temperature Range="-40 to 85 C", Rating=Catalog
U9: library part CMP-0050936-4, "Dual-Bit Dual-Supply Bus Transceiver, DQM0008A (X2SON-8)", F @ Nom Voltage(Max)(Mhz)=100, ICC @ Nom Voltage(Max)(mA)=0.0009, Manufacturer="Texas Instruments", Operating Temperature Range(C)="-40 to 85", PartNumber=SN74AVC2T244DQMR, Rating=Catalog, tpd @ Nom Voltage(Max)(ns)=20,7,3.5, Voltage(Nom)(V)=0.9,1.2,1.5,1.8,2.5,3.3
U10: library part CMP-0051795-5, "Enhanced Product Dual Buffer/Driver with Open-Drain Output, DCK0006A (SOT-SC70-6)", F @ Nom Voltage(Max)(Mhz)=150, ICC @ Nom Voltage(Max)(mA)=0.01, Manufacturer="Texas Instruments", Operating Temperature Range(C)="-40 to 125", PartNumber=SN74LVC2G07DSFR, Rating=Catalog, tpd @ Nom Voltage(Max)(ns)=8.6,4.4,3.7,2.9, Voltage(Nom)(V)=1.8,2.5,3.3,5
U11: library part CMP-0032427-3, "Single-Channel Ultra-Small Adjustable Supervisory Circuit With Active-High Open-Drain Output, DRY0006A (USON-6)", Manufacturer="Texas Instruments", Operating Temperature Range="-40 to 125 C", Rating=Catalog, Threshold Voltage 1 (typ)(Typ)(V)=Adjustable
U12: library part CMP-0098162-1, "Optical Jack Transmitter OTJ-8", Manufacturer="Cliff Electronic Components", Max Supply Voltage=5.5V, Min Supply Voltage=2.7V, Operating Temperature Range="-20°C to +70°C", Part Number=FCR684208T, Power_TotalModule=120mW
U13: library part CMP-0066452-2, "4-Bit Dual-Supply Bus Transceiver With Configurable Voltage-Level Shifting and 3-State Outputs, RSV0016A (UQFN-16)", Alternate Manufacturer="Texas Instruments", Operating Temperature Range="-40 to 85 C", Rating=Catalog
U14: library part CMP-0097438-1, "Optical Receiver 25Mbps Single 650nm", Digikey Part Number=1080-PLR237/T10BK-ND, Manufacturer="Everlight Electronics", Max Supply Voltage=5.5V, Min Supply Voltage=3V, Operating Temperature Range="-20°C to +70°C"
U15: library part CMP-0028694-1, "216 kHz Digital Audio Interface Transceiver (DIX) with Stereo ADC and Routing, PCM, S / PDIF, ADC, 4.5 - 5.5V for Analog, 2.9 - 3.6V for DIX, -40 to 85 degC, 48-Pin LQFP (PT), Green (RoHS & no Sb/Br)", Manufacturer="Texas Instruments", Power Supply(V)="4.5-5.5 for Analog, 2.9-3.6 for DIX"
U16 U17 U19: library part CMP-0051024-2, "Single 2-Line to 1-Line Data Selector/Multiplexer, DCT0008A, LARGE T&R", Alternate Manufacturer="Texas Instruments", Alternate PartNumber=SN74LVC2G157DCUT, F @ Nom Voltage(Max)(Mhz)=150, Generic Part Number=SN74LVC2G157, ICC @ Nom Voltage(Max)(mA)=0.01, Operating Temperature Range(C)="-40 to 85", PartNumber=SN74LVC2G157DCTR, Rating=Catalog, tpd @ Nom Voltage(Max)(ns)=14,8,6,4, Voltage(Nom)(V)=1.8,2.5,3.3,5
U18: library part CMP-0051641-4, "Single Schmitt-Trigger Inverter, DCK0005A (SOT-SC70-5)", Alternate Manufacturer="Texas Instruments", Alternate PartNumber=SN74LVC1G14DCKT, F @ Nom Voltage(Max)(Mhz)=150, ICC @ Nom Voltage(Max)(mA)=0.01, Operating Temperature Range="-40 to 125 C", PartNumber=SN74LVC1G14DCKR, Rating=Catalog, tpd @ Nom Voltage(Max)(ns)=11,6.5,5.5,5, Voltage(Nom)(V)=1.8,2.5,3.3,5
U20: library part CMP-0051026-2, "Single 2-Line to 1-Line Data Selector/Multiplexer, DCU0008A, LARGE T&R", Alternate Manufacturer="Texas Instruments", Alternate PartNumber=SN74LVC2G157DCUT, F @ Nom Voltage(Max)(Mhz)=150, Generic Part Number=SN74LVC2G157, ICC @ Nom Voltage(Max)(mA)=0.01, Operating Temperature Range(C)="-40 to 85", PartNumber=SN74LVC2G157DCUR, Rating=Catalog, tpd @ Nom Voltage(Max)(ns)=14,8,6,4, Voltage(Nom)(V)=1.8,2.5,3.3,5
U21: library part CMP-0043157-2, "Low-Voltage 8-Bit I2C and SMBus I/O Expander, 1.65 to 5.5 V, -40 to 85 degC, 16-pin QFN (RGT), Green (RoHS & no Sb/Br)", 5V Tolerant I/O=Yes, Manufacturer="Texas Instruments", Max Frequency(kHz)=400, PartNumber=TCA6408ARGTR
Y1: library part CMP-0096068-1, "Crystal Oscillator 24MHz ±50ppm HCMOS 3.3V SMD 2x1.6mm", Frequency Stability=50ppm, Frequency_Fixed=24MHz, Load Capacitance=15pF, Manufacturer=Abracon, Max Supply Current=5mA, Max Supply Voltage=3.63V, Min Supply Voltage=2.97V, Operating Temperature Range="-40°C to +85°C"
Y2: library part CMP-0004590-3, "Crystal, 24.576 MHz, 10pF, SMD", Frequency_Fixed=24.576MHz, Frequency Stability=+/-20ppm, Manufacturer="Abracon Corporation", Supplier Part Number 1=535-9094-1-ND
ZZ1: library part CMP-0077236-1
ZZ2: library part CMP-0077237-1
ZZ3: library part CMP-0077238-1

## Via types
v1: diameter 20, hole 10, Top Layer to Bottom Layer, tented both sides, 1299 vias
v2: diameter 25, hole 10, Top Layer to Bottom Layer, tented both sides, 87 vias
v3: diameter 23.62, hole 11.81, Top Layer to Bottom Layer, 12 vias
v4: diameter 19.68, hole 7.87, Top Layer to Bottom Layer, 7 vias
v5: diameter 20, hole 10, Top Layer to Bottom Layer, 6 vias

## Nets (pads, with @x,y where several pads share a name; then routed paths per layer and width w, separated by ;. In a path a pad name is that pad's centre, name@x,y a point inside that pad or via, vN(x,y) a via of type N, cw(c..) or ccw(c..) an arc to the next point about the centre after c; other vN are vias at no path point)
1.0V: C59.1 C60.1 C61.1 C65.2 C66.2 C67.2 C68.2 C69.2 C70.2 C71.2 C72.2 C73.2 C74.2 C75.2 C76.2 C77.2 C78.2 L6.2 R34.2 R40.1 R54.1 U6.11 U6.16 U6.17 U6.24 U6.36 U6.41 U6.49 U6.56 U6.60 U6.73 U6.80 U6.81 U6.87 U6.101 U6.102 U6.120 U6.126 | length 3405.1
  Top Layer w7.87: C68.2@713.58,1377.95 v2(748.03,1377.95) ; C69.2@713.58,1432.09 v2(748.03,1432.09) ; C70.2@713.58,1579.72 716.54,1582.68 v2(750,1582.68) ; C71.2@713.58,1692.91 v2(748.03,1692.91) ; C72.2@713.58,1756.89 714.57,1755.91 v2(747.05,1755.91) v2@748.03,1754.92 ; C67.2@866.14,1304.13 v2(866.14,1338.58) ; v2(866.14,1811.02) C73.2@866.14,1845.47 ; C66.2@984.25,1304.13 v2(984.25,1338.58) ; v2(984.25,1811.02) C74.2@984.25,1845.47 ; C65.2@1072.83,1304.13 1077.76,1309.06 v2(1077.76,1338.58) ; v2(1086.61,1812.01) 1086.61,1844.49 C75.2@1087.6,1845.47 ; v2@1220.47,1361.22 v2(1221.46,1362.2) v2@1222.44,1363.19 ; v2(1220.47,1456.69) C77.2@1254.92,1456.69 ; v2(1222.44,1740.16) 1252.95,1740.16 C76.2@1254.92,1742.13 1254.92,1778.54 R40.1@1251.97,1781.5 ; C78.2@1253.94,1362.2 C78.2@1254.92,1363.19
  Copper Layer 3 w19.68: v2(187.01,816.93) 187.01,600.39 246.06,541.34 1028.54,541.34 1259.84,772.64 1259.84,885.83 ; v1(1259.84,1008.86) 1259.84,885.83 ; v1(1407.48,885.83) 1259.84,885.83
  Bottom Layer w7.87: U6.36@681.1,1377.95 v2(748.03,1377.95) ; U6.41@681.1,1456.69 723.43,1456.69 v2(748.03,1432.09) ; U6.49@681.1,1582.68 v2(750,1582.68) ; U6.56@681.1,1692.91 v2(748.03,1692.91) ; U6.60@681.1,1755.91 v2(747.05,1755.91) ; U6.24@866.14,1271.65 v2(866.14,1338.58) ; v2(866.14,1811.02) U6.73@866.14,1877.95 ; U6.17@976.38,1271.65 U6.16@992.13,1271.65 992.13,1311.02 984.25,1318.9 v2(984.25,1338.58) ; U6.80@976.38,1877.95 U6.81@992.13,1877.95 992.13,1838.58 984.25,1830.71 v2(984.25,1811.02) ; U6.11@1070.87,1271.65 1070.87,1312.01 1077.76,1318.9 v2(1077.76,1338.58) ; v2(1086.61,1812.01) U6.87@1086.61,1877.95 ; v2(1220.47,1456.69) U6.120@1287.4,1456.69 ; v2(1221.46,1362.2) U6.126@1287.4,1362.2 ; v2(1222.44,1740.16) U6.102@1287.4,1740.16 U6.101@1287.4,1755.91
  Bottom Layer w9.84: v2(187.01,816.93) R54.1@223.23,816.93 v2(187.01,816.93)
  Bottom Layer w19.68: v1(1407.48,885.83) R34.2@1448.82,885.83
  other v1: 1235.24,1023.62 1259.84,1033.46 1235.24,1048.23 1259.84,1058.07
1.8V: C63.2 C91.2 C92.2 J26.1 U5.5 U8.3 U9.8 | length 995.8
  Copper Layer 3 w19.68: v2(1476.38,1336.61) 1730.31,1336.61 1756.89,1363.19 1771.65,1377.95 1771.65,1425.59 ; v1(1574.8,1614.17) 1574.8,1594.49 v1(1653.54,1515.75) 1653.54,1476.38 1704.33,1425.59 1771.65,1425.59 ; J26.1@1870.08,1425.59 1771.65,1425.59
  Bottom Layer w7.87: C91.2@1474.41,1370.08 U9.8@1474.41,1403.54
  Bottom Layer w9.84: C91.2@1474.41,1370.08 1476.38,1368.11 C91.2@1476.38,1366.14 ; U8.3@1647.64,1440.94 1647.64,1485.24 C92.2@1653.54,1491.14 v1(1653.54,1515.75)
  Bottom Layer w19.68: v2(1476.38,1336.61) C91.2@1476.38,1366.14 ; v1(1574.8,1614.17) C63.2@1604.33,1614.17 1650.59,1614.17 U5.5@1655.51,1619.09
3.3V: C43.1 C44.2 C45.2 C46.2 C47.2 C48.2 C49.2 C50.2 C51.2 C52.2 C53.2 C54.2 C55.2 C56.2 C57.2 C58.1 C62.1 C81.2 C85.2 C86.2 C88.2 C89.2 C90.2 C93.1 C94.1 C95.1 C96.1 C97.1 C100.1 C101.1 C104.1 C114.1 C115.1 C116.1 C117.1 J26.3 R32.2 R33.1 R36.1 R37.1 R38.1 R41.2 R45.2 R50.1 R51.1 R55.1 R57.1 R66.2 S2.6 U3.5 U3.6 U4.1 U4.4 U5.1 U5.3 U6.6 U6.14 U6.19 U6.29 U6.42 U6.44 U6.52 U6.67 U6.78 U6.83 U6.92 U6.105 U6.110 U6.111 U7.7 U8.6 U8.7 U9.1 U10.5 U11.1 U11.6 U12.2 U13.5 U13.14 U13.15 U13.16 U14.1 U15.22 U15.36 U15.42 U16.8 U17.8 U18.5 U19.8 Y1.4 | length 11797.5
  Top Layer w7.87: C49.2@713.58,1471.46 714.57,1472.44 v2(747.05,1472.44) ; C48.2@713.58,1505.91 715.55,1503.94 v2(750,1503.94) ; C50.2@713.58,1628.94 714.57,1629.92 v2(747.05,1629.92) ; v2(771.65,1812.01) 771.65,1844.49 C51.2@772.64,1845.47 ; C47.2@787.4,1304.13 v2(787.4,1338.58) ; v1(895.86,944.88) 933.07,944.88 R45.2@935.04,942.91 ; C46.2@944.88,1304.13 v2(944.88,1338.58) ; v2(944.88,1811.02) C52.2@944.88,1845.47 ; C45.2@1023.62,1304.13 v2(1023.62,1338.58) ; v2(1023.62,1811.02) C53.2@1023.62,1845.47 ; C44.2@1146.65,1304.13 1149.61,1307.09 v2(1149.61,1336.61) ; v2(1165.35,1812.01) 1165.35,1844.49 C54.2@1166.34,1845.47 ; v2(1220.47,1614.17) C56.2@1254.92,1614.17 ; v1(1294.29,2386.81) 1305.12,2397.64 U13.5@1305.12,2413.39 ; v1(1309.06,2568.9) C95.1@1309.06,2539.37 1305.12,2535.43 U13.16@1305.12,2507.87 U13.15@1320.87,2507.87 U13.14@1336.61,2507.87
  Top Layer w9.84: R32.2@359.25,2079.72 v1@402.11,2122.58 ; v2(393.7,600.39) R50.1@393.7,646.46 ; v2(467.52,2785.43) U15.22@522.64,2785.43 ; R66.2@757.87,2593.5 794.29,2593.5 C96.1@797.24,2596.46 ; v2(797.24,2554.13) C96.1@797.24,2596.46 ; U15.36@797.24,2687.99 C97.1@797.24,2637.8 799.21,2635.83 C96.1@799.21,2598.43 C96.1@797.24,2596.46 ; v1(797.24,2854.33) 807.09,2844.49 U15.42@855.32,2844.49 ; v1(949.8,3159.45) 1009.65,3099.61 S2.6@1081.1,3099.61 ; v2(1220.47,1678.15) C55.2@1254.92,1678.15
  Copper Layer 3 w7.87: v1(1294.29,2386.81) 1294.29,2519.68 1309.06,2534.45 v1(1309.06,2568.9)
  Copper Layer 3 w9.84: v2(1437.01,1336.61) 1437.01,1284.45 1461.61,1259.84 v1(1500.98,1259.84)
  Copper Layer 3 w19.68: U14.1@282.28,2462.2 282.28,2656.02 344.49,2718.22 344.49,2790.16 ; v2(285.43,698.82) 285.43,634.84 319.88,600.39 v2(393.7,600.39) 442.91,649.61 442.91,738.19 v2(492.13,787.4) v2(492.13,836.61) 600.39,944.88 v1(895.86,944.88) 944.88,993.9 v2(944.88,1338.58) ; v2(467.52,2785.43) 349.21,2785.43 344.49,2790.16 ; 620.08,2047.24 v2(688.98,2047.24) 767.72,2047.24 821.85,1993.11 885.83,1993.11 ; v2(787.4,1161.42) v2(787.4,1338.58) ; 866.14,3021.65 856.3,3031.5 v2(374.02,3031.5) 374.02,2948.03 280.32,2854.33 344.49,2790.16 ; v2(885.83,2047.24) 885.83,1993.11 ; 1082.68,1998.03 v2(1082.68,2047.24) ; v2@1151.57,1338.58 1151.57,1387.8 1176.18,1412.4 1392.72,1412.4 1437.01,1368.11 1437.01,1338.58 v2(1437.01,1336.61) ; v2(1220.47,1614.17) 1387.8,1614.17 1418.34,1644.71 1642.69,1644.71 1732.28,1555.12 v1(1732.28,1515.75) ; 1240.16,1486.22 1471.46,1486.22 v2(1491.14,1505.91) ; v2(1279.53,2047.24) 1225.39,1993.11 885.83,1993.11 ; v1(1422.24,920.28) 1461.61,920.28 ; v1(1555.12,1053.15) 1500.98,999.02 1500.98,959.65 1461.61,920.28 ; v1(1584.65,1053.15) 1584.65,1008.86 1633.86,959.65 v1(1904.53,959.65) ; v1(1624.02,720.55) 1624.02,760.08 1602.38,781.72 1538.48,781.72 1461.61,858.58 1461.61,920.28 ; v2(1653.54,1840.55) 1653.54,1786.42 1712.6,1727.36 v2(1771.65,1727.36)
  Copper Layer 3 w29.53: 905.51,2637.8 974.41,2568.9 v1(1309.06,2568.9) ; v2(1149.61,1336.61) 1149.61,1271.65 1240.16,1181.1 1505.91,1181.1 1555.12,1131.89 v1(1555.12,1053.15) ; 1199.7,1781.5 1258.75,1840.55 v2(1653.54,1840.55) 1766.85,1840.55 1870.08,1737.32 J26.3@1870.08,1625.59
  Bottom Layer w5.91: U10.5@456.3,787.4 U10.5@458.66,787.4 v2(492.13,787.4)
  Bottom Layer w7.87: v2(285.43,698.82) 285.43,738.19 284.45,739.17 U11.1@284.45,767.72 U11.6@307.09,767.72 ; R55.1@455.91,836.61 v2(492.13,836.61) ; R41.2@605.32,1653.54 625,1653.54 648.62,1629.92 U6.52@681.1,1629.92 v2(747.05,1629.92) ; U6.42@681.1,1472.44 v2(747.05,1472.44) ; U6.44@681.1,1503.94 v2(750,1503.94) ; v2(771.65,1812.01) U6.67@771.65,1877.95 ; v2(787.4,1161.42) 816.93,1161.42 R36.1@821.85,1166.34 ; U6.29@787.4,1271.65 v2(787.4,1338.58) ; U6.19@944.88,1271.65 v2(944.88,1338.58) ; v2(944.88,1811.02) U6.78@944.88,1877.95 ; U6.14@1023.62,1271.65 v2(1023.62,1338.58) ; v2(1023.62,1811.02) U6.83@1023.62,1877.95 ; U6.6@1149.61,1271.65 v2(1149.61,1336.61) ; v2(1165.35,1812.01) U6.92@1165.35,1877.95 ; v2(1220.47,1614.17) U6.110@1287.4,1614.17 U6.111@1287.4,1598.43 ; v2(1220.47,1678.15) 1235.24,1692.91 U6.105@1287.4,1692.91 ; Y1.4@1395,1300 1403.88,1303.33 C85.2@1442.91,1303.15 ; C89.2@1437.01,1368.11 1438.98,1370.08 U9.1@1438.98,1403.54
  Bottom Layer w9.84: U14.1@282.28,2462.2 342.91,2462.2 C93.1@344.49,2460.63 ; v2(374.02,3031.5) C104.1@408.46,3031.5 409.45,3032.48 U18.5@447.83,3032.48 ; C81.2@467.52,2746.06 v2(467.52,2785.43) ; v2(492.13,787.4) C117.1@526.57,787.4 ; v2(688.98,2047.24) C115.1@728.35,2047.24 728.35,2052.17 747.84,2071.66 747.84,2086.42 U19.8@749.02,2087.6 ; C101.1@728.35,2852.36 765.75,2852.36 C100.1@767.72,2854.33 v1(797.24,2854.33) ; v2(885.83,2047.24) C116.1@925.2,2047.24 925.2,2052.17 944.69,2071.66 944.69,2086.42 U16.8@945.87,2087.6 ; v2(1082.68,2047.24) C88.2@1122.05,2047.24 1122.05,2052.17 1141.54,2071.66 1141.54,2086.42 U17.8@1142.72,2087.6 ; v2(1279.53,2047.24) C114.1@1318.9,2047.24 C114.1@1318.9,2052.17 ; v1(1422.24,920.28) U4.1@1422.24,944.88 ; C89.2@1437.01,1368.11 v2(1437.01,1336.61) 1437.01,1318.9 1446.85,1309.06 C85.2@1446.85,1304.13 C85.2@1446.85,1299.21 ; R51.1@1459.84,1505.91 v2(1491.14,1505.91) ; R57.1@1474.61,1259.84 v1(1500.98,1259.84) ; R38.1@1584.65,720.55 v1(1624.02,720.55) R37.1@1663.39,720.55 ; v1(1732.28,1515.75) C90.2@1732.28,1491.14 1724.41,1483.27 U8.6@1724.41,1440.94 U8.7@1750,1440.94 ; U7.7@1834.65,974.41 1860.24,974.41 C57.2@1875,959.65
  Bottom Layer w10: Y1.4@1393.54,1299.21 1394.33,1300 Y1.4@1395,1300
  Bottom Layer w19.68: U12.2@280.32,2854.33 C94.1@344.49,2854.33 ; v2(1653.54,1840.55) 1653.54,1793.31 1655.51,1791.34 U5.1@1655.51,1727.36 ; U5.3@1732.28,1727.36 v2(1771.65,1727.36) ; C57.2@1875,959.65 v1(1904.53,959.65)
  other v1: 497.05,2091.54 497.05,2116.14 403.54,2124.14 497.05,2140.75 403.54,2148.75 442.91,2170.28 920.28,3159.45 935.04,3179.13
3.3V-TP: J21.1 R33.2
5V-SPDIF: C98.1 C99.1 L7.2 R31.1 U15.46 | length 1993
  Top Layer w9.84: v1(797.24,2937.99) 812.01,2923.23 U15.46@855.32,2923.23
  Top Layer w19.68: v1(285.43,1702.76) 343.5,1702.76 L7.2@344.49,1703.74
  Top Layer w40: v1(298.87,1763.13) R31.1@343.16,1763.13
  Copper Layer 3 w19.68: v1(285.43,1702.76) 285.43,1749.7 v1(298.87,1763.13) 221.87,1763.13 110,1875 110,2137.5 147.5,2175 314.76,2175 393.7,2253.94 393.7,2506.97 430.22,2543.48 430.22,2570.96 v1(797.24,2937.99)
  Bottom Layer w9.84: C98.1@728.35,2960.63 736.22,2952.76 752.95,2952.76 757.87,2947.83 C99.1@767.72,2937.99 v1(797.24,2937.99)
5V-U3: C42.2 J19.1 R31.2 U3.3 U3.4
  other v1: 245,1837.5 196.85,1887.5 196.85,1952.5 191.93,2091.54 280.51,2091.54 206.69,2116.14 265.75,2116.14 191.93,2140.75 280.51,2140.75
9211-LOCK: U15.1 U18.2 | length 333
  Top Layer w9.84: v2(777.56,3075.79) 797.24,3056.1 U15.1@797.24,3020.67
  Bottom Layer w9.84: U18.2@536.42,3006.89 570.87,3006.89 639.76,3075.79 v2(777.56,3075.79)
\PDN: C22.1 J9.1 R5.1 R7.1 R80.2 S1.5 TP4.1 U1.4 | length 4795.5
  Top Layer w9.84: U1.4@3153.72,1855.29 v1(3199.11,1855.29)
  Top Layer w10: S1.5@2386.29,426.08 2534.92,426.08 R7.1@2535.5,425.5 2541.18,431.18 v1@2603.5,431.18
  Bottom Layer w9.84: R80.2@1553.15,2864.17 v1(1594.49,2864.17) ; v1(2602.5,430) 2657.5,485 2715,485 2820.55,590.55 3005.55,590.55 3092.5,677.5 3092.5,772.82 3148.5,828.82 3148.5,1408.65 3331.72,1591.87 3331.72,1724.23 3229.82,1826.14 R5.1@3229.82,1855.29 v1(3199.11,1855.29)
  Bottom Layer w10: v1(1594.49,2864.17) 2150.72,2864.17 2208.28,2806.61 2208.28,2365.34 2164.2,2321.26 TP4.1@2164.2,2211.5 2164.2,2044.14 J9.1@2156.62,2036.56 2173.18,2020 3011.62,2020 3176.34,1855.29 v1(3199.11,1855.29)
\TRST: R48.1 U6.123 | length 144.1
  Bottom Layer w7.87: U6.123@1287.4,1409.45 1340.55,1409.45 1363.19,1432.09 1363.19,1457.87 R48.1@1386.61,1481.3
ADR: J8.2 U1.13 | length 1153.8
  Top Layer w10: J8.2@2082.31,1499.37 2229.17,1499.37 2384.8,1655 3060,1655 3090.03,1624.97 U1.13@3153.72,1624.97 U1.13@3149.86,1628.83
AMP_SCL: J11.2 J22.1 TP19.1 U1.5 | length 3194.2
  Top Layer w10: TP19.1@1413,550 J22.1@1413,372 1761.45,372 2190,800.55 2190,895.35 J11.2@2127.41,957.95 ; v1(3092.5,1829.69) U1.5@3153.72,1829.69
  Bottom Layer w9.84: J11.2@2127.41,957.95 2118.78,957.95 2058.79,1017.93 2058.79,1117.58 1952.65,1223.72 1952.65,1307.93 1970.96,1326.24 2143.14,1326.24 2550.8,1733.9 3054.28,1733.9 3092.5,1772.12 v1(3092.5,1829.69)
AMP_SDA: J10.2 J23.1 TP20.1 U1.6 | length 3042.1
  Top Layer w9.84: TP20.1@1195,545 1250,545 1490,785 1695,785 1720,810 1720,895 1756.42,931.42 1951.38,931.42 1980.41,960.45 J10.2@1980.41,960.95 ; v1(3061.88,1804.1) U1.6@3153.72,1804.1
  Top Layer w10: J23.1@1195,375 TP20.1@1195,545
  Bottom Layer w9.84: J10.2@1980.41,960.95 2036.01,1016.55 2036.01,1103.08 1932.55,1206.54 1932.55,1318.56 1961.68,1347.7 2132.82,1347.7 2545.12,1760 3048.6,1760 3062.5,1773.9 3062.5,1803.48 v1(3061.88,1804.1)
BCLK-XMOS: R43.2 R52.2 U16.2 | length 2406.7
  Top Layer w9.84: v2(537.5,1917.5) 613.11,1993.11 v2(757.87,1993.11) 757.87,2137.75 815,2194.88 v2(989.17,2194.88)
  Bottom Layer w7.87: v2@537.5,1915 537.5,1669.39 450.63,1582.52 450.63,1074.96 738.19,787.4 R52.2@1120.87,787.4
  Bottom Layer w9.84: R43.2@757.87,1958.66 v2(757.87,1993.11) ; U16.2@971.46,2243.11 971.46,2212.6 v2(989.17,2194.88)
BIAS: C33.2 C34.1 L5.1 R12.2 R13.2 R16.1 U2.1 U2.2 | length 1810.7
  Top Layer w9.84: L5.1@2040.17,3875.65 v1(2040.17,3904.59) ; v1(2500.17,4605.65) R13.2@2536.67,4605.65 2536.67,4661.71 R16.1@2540.6,4665.65
  Copper Layer 3 w9.84: 2419.67,4525.15 v1(2500.17,4605.65)
  Copper Layer 3 w10: v1(2040.17,3904.59) 2040.17,4044.65 2296.17,4300.65 2296.17,4401.65 2419.67,4525.15
  Copper Layer 3 w50: 2017.17,3824.65 2110.17,3824.65 2329.17,4043.65 2329.17,4213.65 2419.17,4303.65 2511.17,4303.65
  other v1: 1700.17,3770.65 1725.17,3770.65 1750.17,3770.65 1775.17,3770.65 1800.17,3770.65 1825.17,3770.65 1850.17,3770.65 1875.17,3770.65 1900.17,3770.65 1925.17,3770.65 1950.17,3770.65 1975.17,3770.65 2520.17,4280.65 2547.67,4280.65 2575.17,4280.65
